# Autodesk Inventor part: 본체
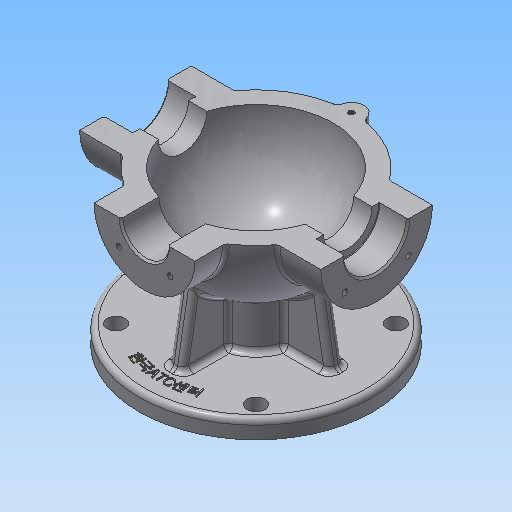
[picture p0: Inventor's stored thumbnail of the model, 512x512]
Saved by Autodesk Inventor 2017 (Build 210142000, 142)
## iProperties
Created: 2015-12
Part Number: 본체
Material: 알루미늄 6061
Document SubType Name: Modeling
Designer: mduedu
Density: 2.71 g/cm^3
Appearance: 알루미늄 - 평지
Mass: 966.367 g
Surface Area: 788.536 cm^2
Volume: 356.593 cm^3
Author: mduedu
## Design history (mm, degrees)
sketch "스케치1"
  geometry: L1 (-53, 0)-(53, 0); A1 r 53 centre (0, 0) between (53, 0) and (-53, 0); 2 further points
  constraints: 2 coincident, 2 end point, 2 point on circle, 1 centre point, 1 horizontal, 1 midpoint
  dimensions: "d0" = 53 radius of A1
revolve "회전1" sketch "스케치1" stored, may be unused: angle "d2" = 90 deg
feature "쉘1" dims "d11" = 10
node "작업 평면1"
sketch "스케치2"
  geometry: C1 r 31 at (0, 0); 1 further point
  constraints: 1 centre point, 1 coincident
  dimensions: "d4" = 62 diameter of C1
extrude "돌출1" join sketch "스케치2" stored distance "d5" = 10; taper "d6" = 0 deg
node "작업 평면2"
sketch "스케치3"
  geometry: C1 r 28 at (0, 0); 1 further point
  constraints: 1 centre point, 1 coincident
  dimensions: "d8" = 56 diameter of C1
extrude "돌출2" join sketch "스케치3" stored distance "d9" = 10; taper "d10" = 0 deg
hole "구멍1" diameter "d14" = 35; stored, may be unused: countersink angle "d18" = 90 deg, drill point angle "d20" = 0 deg; dims "d12" = 10, "d13" = 10, "d15" = 6, "d16" = 4, "d17" = 2, "d19" = 16
hole "구멍2" diameter "d23" = 27; stored, may be unused: countersink angle "d27" = 90 deg, drill point angle "d29" = 0 deg; dims "d21" = 10, "d22" = 10, "d24" = 6, "d25" = 4, "d26" = 2, "d28" = 16
fillet "모깎기1" dims "d30" = 0.3
hole "구멍3" diameter "d33" = 26; stored, may be unused: countersink angle "d37" = 90 deg, drill point angle "d39" = 0 deg; dims "d31" = 10, "d32" = 10, "d34" = 6, "d35" = 4, "d36" = 2, "d38" = 16
chamfer "모따기1" distance "d40" = 1; stored, may be unused: second distance "d41" = 2, angle "d42" = 45 deg
sketch "스케치4"
  geometry: L1 (0, 0)-(0, -25); L2 (0, 0)-(-17.678, -17.678); A1 r 25 centre (0, 0) between (-17.678, -17.678) and (0, -25); 1 further point
  constraints: 4 end point, 2 point on circle, 1 centre point, 1 coincident, 1 vertical
  dimensions: "d43" = 50 diameter of A1; "d47" = 45 deg angle of L1 L2
hole "구멍4" sketch "스케치4" at (-17.678, -17.678) diameter "d49" = 3.242; stored, may be unused: countersink angle "d53" = 90 deg, drill point angle "d55" = 118 deg; dims "d50" = 11, "d51" = 4, "d52" = 2, "d54" = 13
sketch "스케치5"
  geometry: L1 (0, 0)-(0, -20); L2 (0, 0)-(-14.142, -14.142); A1 r 20 centre (0, 0) between (0, -20) and (-14.142, -14.142); 2 further points
  constraints: 4 end point, 2 coincident, 2 point on circle, 1 centre point, 1 vertical
  dimensions: "d59" = 40 diameter of A1; "d65" = 45 deg angle of L1 L2
hole "구멍5" sketch "스케치5" at (-14.142, -14.142) diameter "d67" = 3.242; stored, may be unused: countersink angle "d71" = 90 deg, drill point angle "d73" = 118 deg; dims "d68" = 8, "d69" = 4, "d70" = 2, "d72" = 10
node "작업 평면3"
sketch "스케치6"
  geometry: C1 r 65 at (0, 0); 1 further point
  constraints: 1 centre point, 1 coincident
  dimensions: "d78" = 130 diameter of C1
extrude "돌출3" join sketch "스케치6" distance "d80" = 10; taper "d81" = 0 deg
sketch "스케치7"
  geometry: C1 r 20 at (0, 0); 1 further point
  constraints: 1 centre point, 1 coincident
  dimensions: "d82" = 40 diameter of C1
extrude "돌출4" join sketch "스케치7" stored distance "d84" = 10; taper "d85" = 0 deg
sketch "스케치8"
  geometry: 2 further points
  constraints: 1 coincident
hole "구멍6" sketch "스케치8" at (0, 0) diameter "d86" = 20; stored, may be unused: countersink angle "d90" = 90 deg, drill point angle "d92" = 118 deg; dims "d87" = 7, "d88" = 40, "d89" = 5, "d91" = 10
fillet "모깎기2" dims "d93" = 0.3
sketch "스케치9"
  geometry: L1 (65, -75)-(-65, -75) reference; L2 (-45, -75)-(-38.245, -36.692); A1 r 53 centre (0, 0) between (42.988, 31) and (42.988, -31) reference; 1 further point
  constraints: 2 end point, 1 point on circle, 1 point on line
  dimensions: "d94" = 45 horizontal distance of L2.start point (0, 0); "d95" = 80 deg angle of L2 L1
feature "리브1" sketch "스케치9" dims "d96" = 1, "d97" = 8, "d98" = 0, "d99" = 0, "d100" = 1, "d101" = 1
sketch "스케치10"
  geometry: L1 (0, 0)-(0, -55); L2 (0, 0)-(-38.891, -38.891); A1 r 55 centre (0, 0) between (0, -55) and (-38.891, -38.891); 2 further points
  constraints: 4 end point, 2 coincident, 2 point on circle, 1 centre point, 1 vertical
  dimensions: "d105" = 110 diameter of A1; "d107" = 45 deg angle of L1 L2
hole "구멍7" sketch "스케치10" at (-38.891, -38.891) diameter "d109" = 10; stored, may be unused: countersink angle "d113" = 90 deg, drill point angle "d115" = 118 deg; dims "d110" = 7, "d111" = 40, "d112" = 5, "d114" = 10
fillet "모깎기3" dims "d120" = 3
fillet "모깎기4" dims "d121" = 3, "d122" = 3
fillet "모깎기5" dims "d123" = 3
fillet "모깎기6" dims "d124" = 3
sketch "스케치11"
  geometry: C1 r 5 at (-38.891, 38.891) reference; C2 r 5 at (38.891, 38.891) reference; C3 r 5 at (38.891, -38.891) reference; C4 r 5 at (-38.891, -38.891) reference; C5 r 20 at (0, 0) reference; C6 r 65 at (0, 0) reference; 1 further point
  constraints: 3 other
feature "엠보싱1" sketch "스케치11" dims "d125" = 0.5, "d126" = 0
sketch "스케치12"
  geometry: L1 (0, 100)-(0, -100); L2 (0, 100)-(100, 100); L3 (100, 100)-(100, -100); L4 (100, -100)-(0, -100); 2 further points
  constraints: 8 end point, 3 perpendicular, 1 coincident, 1 midpoint, 1 vertical
  dimensions: "d127" = 200 distance of L2.end L3.end; "d129" = 100 distance between parallel lines of L1 L3
extrude "돌출5" cut sketch "스케치12" stored distance "d130" = 10; taper "d131" = 0 deg
sketch "스케치13"
  geometry: C1 r 7 at (0, 53); A1 r 53 centre (0, 0) between (42.113, 32.179) and (-42.113, 32.179) reference; 1 further point
  constraints: 1 centre point, 1 point on circle
  dimensions: "d132" = 14 diameter of C1
extrude "돌출6" join sketch "스케치13" distance "d134" = 15; taper "d135" = 0 deg
hole "구멍8" diameter "d139" = 3.242; stored, may be unused: countersink angle "d143" = 90 deg, drill point angle "d145" = 118 deg; dims "d140" = 8, "d141" = 4, "d142" = 2, "d144" = 10, "d148" = 10, "d149" = 10
fillet "모깎기7" dims "d146" = 3
fillet "모깎기8" dims "d147" = 3
node "솔리드1"
mirror "대칭1"
mirror "대칭2"
pattern_circular "원형 패턴1" dims angle "d57" = 360 deg
mirror "대칭3"
pattern_circular "원형 패턴2" dims angle "d75" = 360 deg
pattern_circular "원형 패턴3" dims angle "d103" = 360 deg
pattern_circular "원형 패턴4" dims angle "d118" = 360 deg
node "투영된 루프1"
other parameters: "d3" = 67, "d7" = 62, "d77" = -85
